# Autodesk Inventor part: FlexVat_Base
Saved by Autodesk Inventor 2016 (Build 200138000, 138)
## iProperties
Created: 2015-11
Part Number: FlexVat_Base
Material: Generic
Document SubType Name: Modeling
Designer: John
Density: 1 g/cm^3
Appearance: Default
Author: John
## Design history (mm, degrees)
feature "Base1"
body "Solid1"
